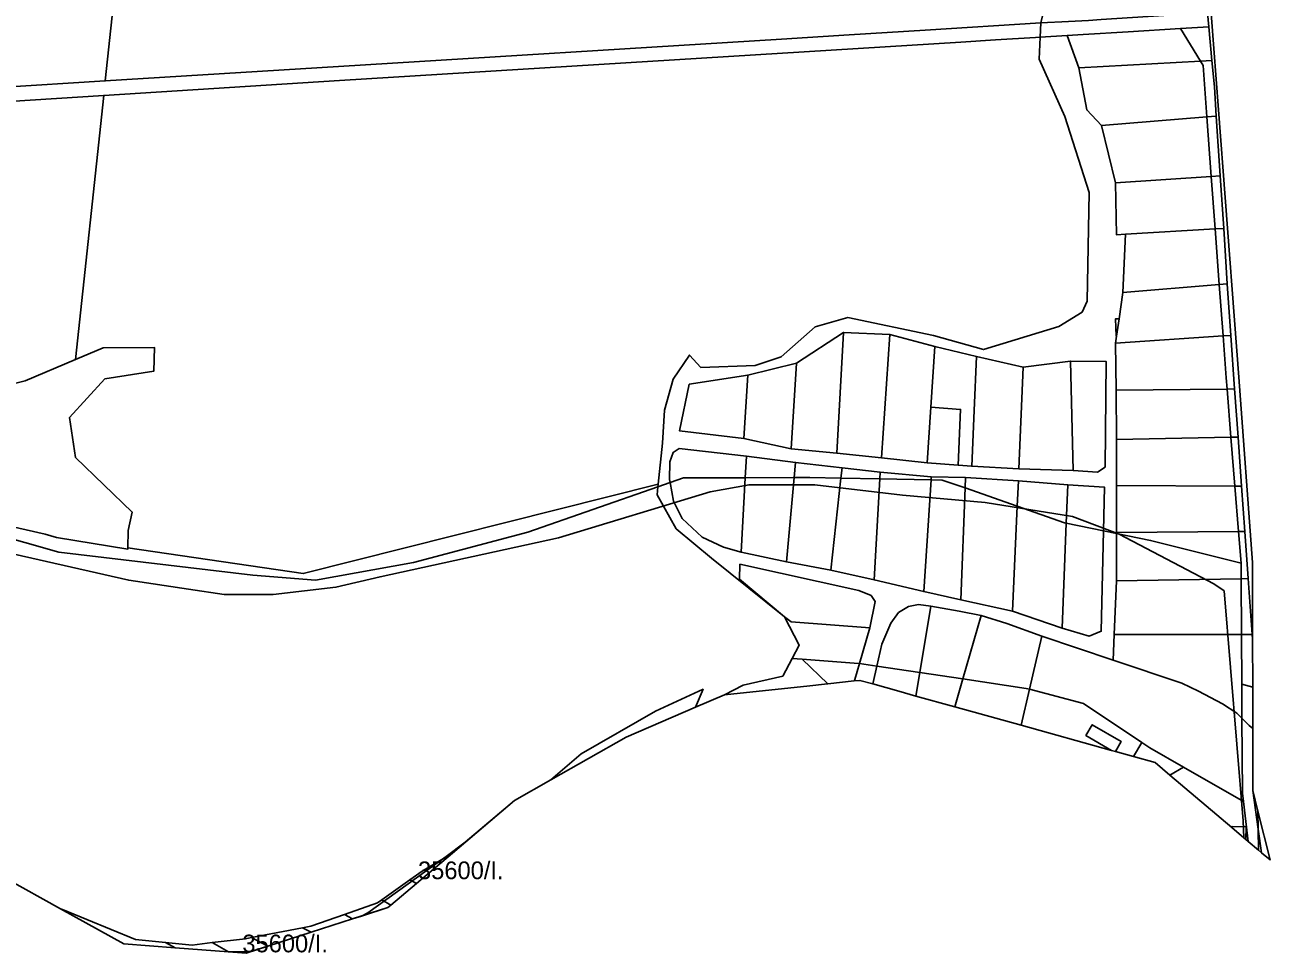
# Model space of a CAD drawing. Extents: x -537068 to -534056, y -1176840 to -1172401.
# Drawn here: x -535510.5 to -535158.7, y -1176840.3 to -1176578.1 of the extents above; entities that cross this region are included whole.
import ezdxf

# ---------------------------------------------------------------- set-up
doc = ezdxf.new("R2010")
doc.units = 0
for name, color, linetype in [('95630013', 7, 'Continuous'), ('95640013', 7, 'Continuous'), ('95660013', 7, 'Continuous')]:
    doc.layers.add(name, color=color, linetype=linetype)

msp = doc.modelspace()

# ---------------------------------------------------------------- linework, layer by layer
at = {"layer": '95630013'}
for points in [[(-535481.66, -1176536.93), (-535472.29, -1176540.41), (-535438.98, -1176545.89), (-535409.88, -1176540.34), (-535372.98, -1176516.36), (-535347.18, -1176505.79), (-535302.92, -1176487.67), (-535283.68, -1176476.52), (-535275.78, -1176469.69), (-535274.71, -1176470.43), (-535254.68, -1176465.39), (-535243.6, -1176462.73), (-535231.98, -1176465.74), (-535216.08, -1176481.68), (-535214.91, -1176500.06), (-535213.95, -1176515.16), (-535217.22, -1176552.4), (-535223.43, -1176577.55), (-535256.14, -1176579.59), (-535277.65, -1176580.92), (-535296.77, -1176582.11), (-535421.85, -1176589.87), (-535487.75, -1176593.96)], [(-535611.19, -1176513.92), (-535537.73, -1176516.12), (-535481.66, -1176536.93), (-535487.75, -1176593.96), (-535547.63, -1176597.67), (-535617.46, -1176602.04), (-535616.99, -1176606.16), (-535547.67, -1176601.79), (-535488.18, -1176598.05), (-535496.14, -1176672.63), (-535510.43, -1176678.69), (-535538.74, -1176685.61), (-535560.3, -1176696.02), (-535567.5, -1176700.1), (-535587.32, -1176690.88), (-535593.03, -1176689.8), (-535608.35, -1176682.47), (-535631.81, -1176671.18), (-535642.41, -1176641.9), (-535625.41, -1176591.75), (-535625.2, -1176543.89)], [(-535616.99, -1176606.16), (-535617.46, -1176602.04), (-535547.63, -1176597.67), (-535487.75, -1176593.96), (-535421.85, -1176589.87), (-535296.77, -1176582.11), (-535277.65, -1176580.92), (-535256.14, -1176579.59), (-535223.43, -1176577.55), (-535223.63, -1176581.58), (-535224.99, -1176581.66), (-535236.23, -1176582.36), (-535246.06, -1176582.97), (-535421.6, -1176593.86), (-535488.18, -1176598.05), (-535547.67, -1176601.79)], [(-535296.79, -1176671.9), (-535304.16, -1176674.29), (-535319.53, -1176674.86), (-535322.75, -1176671.4), (-535327.36, -1176678.19), (-535329.8, -1176686.93), (-535330.38, -1176696.29), (-535331.55, -1176707.87), (-535431.83, -1176733.13), (-535481.42, -1176725.84), (-535481.31, -1176720.98), (-535480.13, -1176715.73), (-535496.15, -1176700.28), (-535497.89, -1176689.03), (-535487.93, -1176678.11), (-535474.03, -1176675.92), (-535473.85, -1176669.28), (-535488.35, -1176669.33), (-535496.14, -1176672.63), (-535488.18, -1176598.05), (-535421.6, -1176593.86), (-535246.06, -1176582.97), (-535236.23, -1176582.36), (-535224.99, -1176581.66), (-535223.63, -1176581.58), (-535223.93, -1176587.8), (-535216.72, -1176603.99), (-535209.82, -1176625.43), (-535210.4, -1176656.13), (-535211.81, -1176659.3), (-535218.36, -1176663.32), (-535239.7, -1176669.83), (-535253.79, -1176665.86), (-535277.94, -1176660.78), (-535287.21, -1176663.4)], [(-535529.02, -1176718.5), (-535520.93, -1176718.34), (-535504.72, -1176722), (-535501.5, -1176722.89), (-535481.43, -1176726.23), (-535481.42, -1176725.84), (-535431.83, -1176733.13), (-535331.55, -1176707.87), (-535331.62, -1176708.58), (-535368.4, -1176721.4), (-535400.69, -1176729.98), (-535428.42, -1176735.02), (-535446.08, -1176733.53), (-535500.92, -1176727.08), (-535529.17, -1176719.06)], [(-535276.15, -1176763.46), (-535283.64, -1176764.25), (-535290.93, -1176757.29), (-535274.93, -1176758.51), (-535274.72, -1176758.54), (-535276.02, -1176763.01)], [(-535274.59, -1176763.29), (-535276.15, -1176763.46), (-535276.02, -1176763.01), (-535274.72, -1176758.54), (-535269.79, -1176759.27), (-535270.82, -1176763.9), (-535270.92, -1176764.31)], [(-535258.73, -1176767.71), (-535263.56, -1176766.36), (-535270.92, -1176764.31), (-535270.82, -1176763.9), (-535269.79, -1176759.27), (-535257.64, -1176761.08)], [(-535247.75, -1176770.77), (-535258.73, -1176767.71), (-535257.64, -1176761.08), (-535245.48, -1176762.88)], [(-535247.75, -1176770.77), (-535245.48, -1176762.88), (-535227.62, -1176765.54), (-535226.65, -1176765.8), (-535229.02, -1176775.98)], [(-535318.86, -1176765.79), (-535321.04, -1176770.89), (-535340.64, -1176779.33), (-535361.87, -1176791.41), (-535353.32, -1176784.03), (-535332.36, -1176771.96)], [(-535191.16, -1176786.53), (-535197.27, -1176784.83), (-535194.93, -1176780.88), (-535192.67, -1176782.39), (-535183.12, -1176787.84), (-535186.99, -1176790.06)], [(-535165.43, -1176804.7), (-535169.44, -1176804.52), (-535169.48, -1176804.89), (-535186.99, -1176790.06), (-535183.12, -1176787.84), (-535166.22, -1176797.48), (-535164.86, -1176808.8), (-535165.57, -1176808.2)], [(-535399.88, -1176820.68), (-535401.69, -1176819.62), (-535398.2, -1176817.14), (-535389.7, -1176812.08)], [(-535407.1, -1176826.78), (-535409.67, -1176825.3), (-535401.69, -1176819.62), (-535399.88, -1176820.68)], [(-535409.67, -1176825.3), (-535407.1, -1176826.78), (-535407.91, -1176827.46), (-535417.88, -1176830.67), (-535420.15, -1176829.4), (-535410.86, -1176826.14)], [(-535470.78, -1176837.3), (-535468.04, -1176838.81), (-535482.5, -1176837.72), (-535500.42, -1176827.8), (-535499.86, -1176827.98), (-535479.2, -1176836.47)], [(-535432, -1176833.2), (-535429.7, -1176832.76), (-535420.15, -1176829.4), (-535417.88, -1176830.67), (-535429.63, -1176834.45)], [(-535446.45, -1176835.95), (-535432, -1176833.2), (-535429.63, -1176834.45), (-535441.88, -1176838.39)], [(-535468.04, -1176838.81), (-535470.78, -1176837.3), (-535463.2, -1176838.05), (-535457.54, -1176837.38), (-535452.94, -1176839.95)], [(-535447.92, -1176840.33), (-535452.94, -1176839.95), (-535457.54, -1176837.38), (-535448.11, -1176836.27), (-535446.45, -1176835.95), (-535441.88, -1176838.39)]]:
    msp.add_lwpolyline(points, close=True, dxfattribs=at)
msp.add_lwpolyline([(-535529.17, -1176719.06), (-535500.92, -1176727.08), (-535446.08, -1176733.53), (-535428.42, -1176735.02), (-535400.69, -1176729.98), (-535368.4, -1176721.4), (-535331.62, -1176708.58), (-535331.85, -1176710.83), (-535326.51, -1176720.46), (-535316.52, -1176728.73), (-535295.86, -1176745.33), (-535291.71, -1176753.33), (-535293.7, -1176757.08), (-535296.36, -1176762.09), (-535307.57, -1176764.65), (-535312.79, -1176767.34), (-535321.04, -1176770.89), (-535318.86, -1176765.79), (-535332.36, -1176771.96), (-535353.32, -1176784.03), (-535361.87, -1176791.41), (-535372.13, -1176797.24), (-535389.7, -1176812.08), (-535398.2, -1176817.14), (-535401.69, -1176819.62), (-535409.67, -1176825.3), (-535410.86, -1176826.14), (-535420.15, -1176829.4), (-535429.7, -1176832.76), (-535432, -1176833.2), (-535446.45, -1176835.95), (-535448.11, -1176836.27), (-535457.54, -1176837.38), (-535463.2, -1176838.05), (-535470.78, -1176837.3), (-535479.2, -1176836.47), (-535499.86, -1176827.98), (-535500.42, -1176827.8), (-535515.98, -1176819.18)], dxfattribs=at)
at = {"layer": '95640013'}
msp.add_lwpolyline([(-535176.57, -1176558.65), (-535171.92, -1176619.39), (-535167.49, -1176677.59), (-535163.64, -1176729.95), (-535163.62, -1176751.68), (-535163.72, -1176750.32), (-535164.86, -1176734.55), (-535165.82, -1176721.23), (-535166.75, -1176708.4), (-535167.75, -1176694.55), (-535168.73, -1176680.96), (-535169.82, -1176665.9), (-535170.78, -1176651.22), (-535171.8, -1176635.6), (-535172.78, -1176620.73), (-535173.88, -1176603.89), (-535174.42, -1176595.65), (-535175.11, -1176588.15), (-535175.97, -1176578.68), (-535176.34, -1176574.66)], dxfattribs=at)
for points in [[(-535223.63, -1176581.58), (-535223.43, -1176577.55), (-535221.6, -1176577.44), (-535217.53, -1176577.23), (-535210.02, -1176576.83), (-535206.44, -1176576.6), (-535184.3, -1176575.17), (-535176.34, -1176574.66), (-535175.97, -1176578.68), (-535184.02, -1176579.16), (-535198.74, -1176580.03), (-535211.52, -1176580.83), (-535215.99, -1176581.11)], [(-535211.52, -1176580.83), (-535198.74, -1176580.03), (-535184.02, -1176579.16), (-535178.39, -1176588.33), (-535212.71, -1176590.22), (-535215.99, -1176581.11)], [(-535175.97, -1176578.68), (-535175.11, -1176588.15), (-535178.39, -1176588.33), (-535184.02, -1176579.16)], [(-535223.93, -1176587.8), (-535223.63, -1176581.58), (-535215.99, -1176581.11), (-535212.71, -1176590.22), (-535210.48, -1176602.15), (-535206.33, -1176606.49), (-535202.37, -1176622.77), (-535202.05, -1176637.45), (-535199.51, -1176637.24), (-535200.27, -1176653.74), (-535201.35, -1176661.12), (-535202.33, -1176661.13), (-535202.16, -1176666.09), (-535202.08, -1176666.09), (-535202.36, -1176667.98), (-535202.17, -1176681.29), (-535202.09, -1176695.22), (-535202.12, -1176708.23), (-535202.1, -1176721.52), (-535202.1, -1176721.79), (-535205.75, -1176721.04), (-535205.47, -1176708.74), (-535215.87, -1176708), (-535229.78, -1176706.91), (-535244.77, -1176705.96), (-535254.42, -1176705.75), (-535268.84, -1176704.5), (-535279.63, -1176703.27), (-535292.74, -1176701.71), (-535306.64, -1176699.94), (-535325.64, -1176697.75), (-535327.37, -1176698.9), (-535328.26, -1176701.54), (-535328.38, -1176706.51), (-535328.21, -1176707.39), (-535331.62, -1176708.58), (-535331.55, -1176707.87), (-535330.38, -1176696.29), (-535329.8, -1176686.93), (-535327.36, -1176678.19), (-535322.75, -1176671.4), (-535319.53, -1176674.86), (-535304.16, -1176674.29), (-535296.79, -1176671.9), (-535287.21, -1176663.4), (-535277.94, -1176660.78), (-535253.79, -1176665.86), (-535239.7, -1176669.83), (-535218.36, -1176663.32), (-535211.81, -1176659.3), (-535210.4, -1176656.13), (-535209.82, -1176625.43), (-535216.72, -1176603.99)], [(-535177.63, -1176589.57), (-535176.55, -1176604.11), (-535206.33, -1176606.49), (-535210.48, -1176602.15), (-535212.71, -1176590.22), (-535178.39, -1176588.33)], [(-535177.63, -1176589.57), (-535178.39, -1176588.33), (-535175.11, -1176588.15), (-535174.42, -1176595.65), (-535173.88, -1176603.89), (-535176.55, -1176604.11)], [(-535206.33, -1176606.49), (-535176.55, -1176604.11), (-535175.31, -1176620.91), (-535202.37, -1176622.77)], [(-535173.88, -1176603.89), (-535172.78, -1176620.73), (-535175.31, -1176620.91), (-535176.55, -1176604.11)], [(-535174.21, -1176635.74), (-535199.51, -1176637.24), (-535202.05, -1176637.45), (-535202.37, -1176622.77), (-535175.31, -1176620.91)], [(-535171.8, -1176635.6), (-535174.21, -1176635.74), (-535175.31, -1176620.91), (-535172.78, -1176620.73)], [(-535174.21, -1176635.74), (-535173.05, -1176651.42), (-535200.27, -1176653.74), (-535199.51, -1176637.24)], [(-535170.78, -1176651.22), (-535173.05, -1176651.42), (-535174.21, -1176635.74), (-535171.8, -1176635.6)], [(-535169.82, -1176665.9), (-535171.97, -1176665.93), (-535173.05, -1176651.42), (-535170.78, -1176651.22)], [(-535173.05, -1176651.42), (-535171.97, -1176665.93), (-535202.36, -1176667.98), (-535202.08, -1176666.09), (-535201.35, -1176661.12), (-535200.27, -1176653.74)], [(-535202.16, -1176666.09), (-535202.33, -1176661.13), (-535201.35, -1176661.12), (-535202.08, -1176666.09)], [(-535205.03, -1176673.17), (-535215.06, -1176673.08), (-535228.44, -1176674.8), (-535241.6, -1176671.83), (-535253.39, -1176668.93), (-535266.16, -1176665.62), (-535279.19, -1176665.01), (-535292.49, -1176673.65), (-535306.26, -1176677.05), (-535322.8, -1176679.63), (-535325.56, -1176692.78), (-535307.4, -1176694.94), (-535293.95, -1176697.87), (-535281.07, -1176699.1), (-535268.44, -1176700.42), (-535255.54, -1176701.84), (-535246.78, -1176702.5), (-535242.99, -1176702.78), (-535229.65, -1176703.56), (-535214.33, -1176704), (-535207.46, -1176704.48), (-535205.27, -1176703.05)], [(-535281.07, -1176699.1), (-535293.95, -1176697.87), (-535292.49, -1176673.65), (-535279.19, -1176665.01)], [(-535279.19, -1176665.01), (-535266.16, -1176665.62), (-535268.44, -1176700.42), (-535281.07, -1176699.1)], [(-535254.51, -1176686.1), (-535255.54, -1176701.84), (-535268.44, -1176700.42), (-535266.16, -1176665.62), (-535253.39, -1176668.93)], [(-535171.09, -1176677.82), (-535170.84, -1176680.99), (-535202.17, -1176681.29), (-535202.36, -1176667.98), (-535171.97, -1176665.93)], [(-535171.09, -1176677.82), (-535171.97, -1176665.93), (-535169.82, -1176665.9), (-535168.73, -1176680.96), (-535170.84, -1176680.99)], [(-535496.15, -1176700.28), (-535480.13, -1176715.73), (-535481.31, -1176720.98), (-535481.42, -1176725.84), (-535481.43, -1176726.23), (-535501.5, -1176722.89), (-535504.72, -1176722), (-535520.93, -1176718.34), (-535529.02, -1176718.5), (-535529.17, -1176719.06), (-535536.34, -1176717.02), (-535564.15, -1176706.5), (-535571.31, -1176702.26), (-535567.5, -1176700.1), (-535560.3, -1176696.02), (-535538.74, -1176685.61), (-535510.43, -1176678.69), (-535496.14, -1176672.63), (-535488.35, -1176669.33), (-535473.85, -1176669.28), (-535474.03, -1176675.92), (-535487.93, -1176678.11), (-535497.89, -1176689.03)], [(-535254.51, -1176686.1), (-535253.39, -1176668.93), (-535241.6, -1176671.83), (-535242.28, -1176687), (-535242.99, -1176702.78), (-535246.78, -1176702.5), (-535246.13, -1176686.72)], [(-535241.6, -1176671.83), (-535228.44, -1176674.8), (-535229.65, -1176703.56), (-535242.99, -1176702.78), (-535242.28, -1176687)], [(-535293.95, -1176697.87), (-535307.4, -1176694.94), (-535306.26, -1176677.05), (-535292.49, -1176673.65)], [(-535229.65, -1176703.56), (-535228.44, -1176674.8), (-535215.06, -1176673.08), (-535214.33, -1176704)], [(-535214.33, -1176704), (-535215.06, -1176673.08), (-535205.03, -1176673.17), (-535205.27, -1176703.05), (-535207.46, -1176704.48)], [(-535306.26, -1176677.05), (-535307.4, -1176694.94), (-535325.56, -1176692.78), (-535322.8, -1176679.63)], [(-535202.09, -1176695.22), (-535202.17, -1176681.29), (-535170.84, -1176680.99), (-535169.75, -1176694.58)], [(-535167.75, -1176694.55), (-535169.75, -1176694.58), (-535170.84, -1176680.99), (-535168.73, -1176680.96)], [(-535246.13, -1176686.72), (-535246.78, -1176702.5), (-535255.54, -1176701.84), (-535254.51, -1176686.1)], [(-535202.12, -1176708.23), (-535202.09, -1176695.22), (-535169.75, -1176694.58), (-535168.64, -1176708.39)], [(-535167.75, -1176694.55), (-535166.75, -1176708.4), (-535168.64, -1176708.39), (-535169.75, -1176694.58)], [(-535306.64, -1176699.94), (-535306.98, -1176706.04), (-535324.38, -1176706.06), (-535328.21, -1176707.39), (-535328.38, -1176706.51), (-535328.26, -1176701.54), (-535327.37, -1176698.9), (-535325.64, -1176697.75)], [(-535293.14, -1176706.02), (-535306.98, -1176706.04), (-535306.64, -1176699.94), (-535292.74, -1176701.71)], [(-535279.95, -1176706.17), (-535288.68, -1176706.02), (-535293.14, -1176706.02), (-535292.74, -1176701.71), (-535279.63, -1176703.27)], [(-535268.94, -1176706.37), (-535279.95, -1176706.17), (-535279.63, -1176703.27), (-535268.84, -1176704.5)], [(-535202.7, -1176750.35), (-535202.98, -1176757.61), (-535223.17, -1176750.83), (-535233.07, -1176747.2), (-535240.33, -1176744.93), (-535246.56, -1176743.69), (-535254.55, -1176742.29), (-535258.05, -1176741.88), (-535260.85, -1176742.4), (-535263.65, -1176744.08), (-535265.87, -1176747.08), (-535268.41, -1176753.09), (-535269.79, -1176759.27), (-535274.72, -1176758.54), (-535271.79, -1176748.42), (-535270.25, -1176741), (-535271.42, -1176739.32), (-535274.83, -1176737.85), (-535308.45, -1176730.5), (-535308.59, -1176734.68), (-535295.86, -1176745.33), (-535316.52, -1176728.73), (-535326.51, -1176720.46), (-535331.85, -1176710.83), (-535331.62, -1176708.58), (-535328.21, -1176707.39), (-535327.2, -1176712.65), (-535324.79, -1176717.58), (-535319.1, -1176722.79), (-535313.08, -1176725.67), (-535308.15, -1176727.06), (-535295.31, -1176729.82), (-535282.76, -1176732.18), (-535270.5, -1176734.84), (-535256.55, -1176738.19), (-535246.06, -1176740.51), (-535231.42, -1176743.69), (-535217.4, -1176748.57), (-535209.79, -1176750.8), (-535206.41, -1176749.42), (-535205.75, -1176721.04), (-535202.1, -1176721.79), (-535202.1, -1176735.17)], [(-535328.21, -1176707.39), (-535324.38, -1176706.06), (-535306.98, -1176706.04), (-535308.15, -1176727.06), (-535313.08, -1176725.67), (-535319.1, -1176722.79), (-535324.79, -1176717.58), (-535327.2, -1176712.65)], [(-535293.14, -1176706.02), (-535295.31, -1176729.82), (-535308.15, -1176727.06), (-535306.98, -1176706.04)], [(-535295.31, -1176729.82), (-535293.14, -1176706.02), (-535288.68, -1176706.02), (-535279.95, -1176706.17), (-535282.76, -1176732.18)], [(-535282.76, -1176732.18), (-535279.95, -1176706.17), (-535268.94, -1176706.37), (-535270.5, -1176734.84)], [(-535270.5, -1176734.84), (-535268.94, -1176706.37), (-535254.48, -1176706.62), (-535256.55, -1176738.19)], [(-535254.42, -1176705.75), (-535254.48, -1176706.62), (-535268.94, -1176706.37), (-535268.84, -1176704.5)], [(-535246.06, -1176740.51), (-535256.55, -1176738.19), (-535254.48, -1176706.62), (-535251.31, -1176706.68), (-535244.88, -1176708.93)], [(-535251.31, -1176706.68), (-535254.48, -1176706.62), (-535254.42, -1176705.75), (-535244.77, -1176705.96), (-535244.88, -1176708.93)], [(-535229.78, -1176706.91), (-535230.1, -1176714.11), (-535244.88, -1176708.93), (-535244.77, -1176705.96)], [(-535215.87, -1176708), (-535216.28, -1176718.88), (-535216.76, -1176718.78), (-535230.1, -1176714.11), (-535229.78, -1176706.91)], [(-535231.42, -1176743.69), (-535246.06, -1176740.51), (-535244.88, -1176708.93), (-535230.1, -1176714.11)], [(-535205.75, -1176721.04), (-535216.28, -1176718.88), (-535215.87, -1176708), (-535205.47, -1176708.74)], [(-535202.12, -1176708.23), (-535168.64, -1176708.39), (-535167.62, -1176721.25), (-535202.1, -1176721.52)], [(-535166.75, -1176708.4), (-535165.82, -1176721.23), (-535167.62, -1176721.25), (-535168.64, -1176708.39)], [(-535216.76, -1176718.78), (-535216.28, -1176718.88), (-535217.4, -1176748.57), (-535231.42, -1176743.69), (-535230.1, -1176714.11)], [(-535206.41, -1176749.42), (-535209.79, -1176750.8), (-535217.4, -1176748.57), (-535216.28, -1176718.88), (-535205.75, -1176721.04)], [(-535166.9, -1176730.2), (-535192.47, -1176723.76), (-535202.1, -1176721.79), (-535202.1, -1176721.52), (-535167.62, -1176721.25)], [(-535166.87, -1176734.58), (-535166.9, -1176730.2), (-535167.62, -1176721.25), (-535165.82, -1176721.23), (-535164.86, -1176734.55)], [(-535202.1, -1176735.17), (-535202.1, -1176721.79), (-535192.47, -1176723.76), (-535166.9, -1176730.2), (-535166.87, -1176734.58)], [(-535294.03, -1176746.78), (-535295.86, -1176745.33), (-535308.59, -1176734.68), (-535308.45, -1176730.5), (-535274.83, -1176737.85), (-535271.42, -1176739.32), (-535270.25, -1176741), (-535271.79, -1176748.42)], [(-535166.78, -1176750.32), (-535202.7, -1176750.35), (-535202.1, -1176735.17), (-535166.87, -1176734.58)], [(-535166.87, -1176734.58), (-535164.86, -1176734.55), (-535163.72, -1176750.32), (-535166.78, -1176750.32)], [(-535260.85, -1176742.4), (-535258.05, -1176741.88), (-535254.55, -1176742.29), (-535257.64, -1176761.08), (-535269.79, -1176759.27), (-535268.41, -1176753.09), (-535265.87, -1176747.08), (-535263.65, -1176744.08)], [(-535246.56, -1176743.69), (-535240.33, -1176744.93), (-535245.48, -1176762.88), (-535257.64, -1176761.08), (-535254.55, -1176742.29)], [(-535291.71, -1176753.33), (-535295.86, -1176745.33), (-535294.03, -1176746.78), (-535271.79, -1176748.42), (-535274.72, -1176758.54), (-535274.93, -1176758.51), (-535290.93, -1176757.29), (-535293.7, -1176757.08)], [(-535245.48, -1176762.88), (-535240.33, -1176744.93), (-535233.07, -1176747.2), (-535223.17, -1176750.83), (-535226.65, -1176765.8), (-535227.62, -1176765.54)], [(-535183.67, -1176764.09), (-535178.89, -1176766.33), (-535172.17, -1176769.88), (-535168.13, -1176772.55), (-535166.63, -1176774), (-535166.5, -1176795.11), (-535166.22, -1176797.48), (-535183.12, -1176787.84), (-535192.67, -1176782.39), (-535194.93, -1176780.88), (-535211.39, -1176769.83), (-535226.65, -1176765.8), (-535223.17, -1176750.83), (-535202.98, -1176757.61)], [(-535172.17, -1176769.88), (-535178.89, -1176766.33), (-535183.67, -1176764.09), (-535202.98, -1176757.61), (-535202.7, -1176750.35), (-535166.78, -1176750.32), (-535166.69, -1176764.4), (-535166.63, -1176774), (-535168.13, -1176772.55)], [(-535166.69, -1176764.4), (-535166.78, -1176750.32), (-535163.72, -1176750.32), (-535163.62, -1176751.68), (-535163.61, -1176765.23)], [(-535283.64, -1176764.25), (-535284.58, -1176764.35), (-535288.69, -1176764.79), (-535312.79, -1176767.34), (-535307.57, -1176764.65), (-535296.36, -1176762.09), (-535293.7, -1176757.08), (-535290.93, -1176757.29)], [(-535200.73, -1176780.59), (-535208.91, -1176775.84), (-535210.74, -1176778.85), (-535203.48, -1176783.1), (-535229.02, -1176775.98), (-535226.65, -1176765.8), (-535211.39, -1176769.83), (-535194.93, -1176780.88), (-535197.27, -1176784.83), (-535202.4, -1176783.4)], [(-535163.6, -1176776.92), (-535164.56, -1176776), (-535166.63, -1176774), (-535166.69, -1176764.4), (-535163.61, -1176765.23)], [(-535163.59, -1176794.38), (-535162.06, -1176805.28), (-535161.98, -1176811.24), (-535164.86, -1176808.8), (-535166.22, -1176797.48), (-535166.5, -1176795.11), (-535166.63, -1176774), (-535164.56, -1176776), (-535163.6, -1176776.92)], [(-535208.91, -1176775.84), (-535200.73, -1176780.59), (-535202.4, -1176783.4), (-535203.48, -1176783.1), (-535210.74, -1176778.85)], [(-535163.59, -1176794.38), (-535162.13, -1176800.24), (-535162.06, -1176805.28)], [(-535158.69, -1176814.03), (-535161.12, -1176811.97), (-535162.06, -1176805.28), (-535162.13, -1176800.24)], [(-535169.44, -1176804.52), (-535165.43, -1176804.7), (-535165.57, -1176808.2), (-535169.48, -1176804.89)], [(-535161.98, -1176811.24), (-535162.06, -1176805.28), (-535161.12, -1176811.97)]]:
    msp.add_lwpolyline(points, close=True, dxfattribs=at)
at = {"layer": '95660013'}
for points in [[(-535176.57, -1176558.65), (-535171.92, -1176619.39), (-535167.49, -1176677.59), (-535163.64, -1176729.95), (-535163.62, -1176751.68), (-535163.61, -1176765.23), (-535163.6, -1176776.92), (-535163.59, -1176794.38), (-535162.13, -1176800.24), (-535158.69, -1176814.03), (-535161.12, -1176811.97), (-535161.98, -1176811.24), (-535164.86, -1176808.8), (-535165.57, -1176808.2), (-535166.12, -1176807.73), (-535166.31, -1176803), (-535171.62, -1176738), (-535174.62, -1176736), (-535201.37, -1176722), (-535214.5, -1176717), (-535239.19, -1176713), (-535262.5, -1176711), (-535287.31, -1176708), (-535305.87, -1176708), (-535316.87, -1176710), (-535359.69, -1176723), (-535410.12, -1176734), (-535422.62, -1176737), (-535440.31, -1176739), (-535454.19, -1176739), (-535464.29, -1176737.5), (-535481.12, -1176735), (-535529.81, -1176724)], [(-535529.81, -1176724), (-535481.12, -1176735), (-535464.29, -1176737.5), (-535454.19, -1176739), (-535440.31, -1176739), (-535422.62, -1176737), (-535410.12, -1176734), (-535359.69, -1176723), (-535316.87, -1176710), (-535305.87, -1176708), (-535287.31, -1176708), (-535262.5, -1176711), (-535239.19, -1176713), (-535214.5, -1176717), (-535201.37, -1176722), (-535174.62, -1176736), (-535171.62, -1176738), (-535166.31, -1176803), (-535166.12, -1176807.73), (-535169.48, -1176804.89), (-535186.99, -1176790.06), (-535191.16, -1176786.53), (-535197.27, -1176784.83), (-535202.4, -1176783.4), (-535203.48, -1176783.1), (-535229.02, -1176775.98), (-535247.75, -1176770.77), (-535258.73, -1176767.71), (-535263.56, -1176766.36), (-535270.92, -1176764.31), (-535274.59, -1176763.29), (-535276.15, -1176763.46), (-535283.64, -1176764.25), (-535284.58, -1176764.35), (-535288.69, -1176764.79), (-535312.79, -1176767.34), (-535321.04, -1176770.89), (-535340.64, -1176779.33), (-535361.87, -1176791.41), (-535372.13, -1176797.24), (-535386.08, -1176809.02), (-535391.5, -1176813), (-535413.62, -1176829), (-535415.4, -1176829.87), (-535417.88, -1176830.67), (-535429.63, -1176834.45), (-535441.88, -1176838.39), (-535446.89, -1176840), (-535452.28, -1176840), (-535452.94, -1176839.95), (-535468.04, -1176838.81), (-535482.5, -1176837.72), (-535500.42, -1176827.8), (-535515.98, -1176819.18)]]:
    msp.add_lwpolyline(points, dxfattribs=at)
for points in [[(-535407.91, -1176827.46), (-535415.4, -1176829.87), (-535413.62, -1176829), (-535391.5, -1176813), (-535386.08, -1176809.02), (-535389.7, -1176812.08), (-535399.88, -1176820.68), (-535407.1, -1176826.78)], [(-535446.89, -1176840), (-535447.92, -1176840.33), (-535452.28, -1176840)]]:
    msp.add_lwpolyline(points, close=True, dxfattribs=at)

# ---------------------------------------------------------------- texts
for p in [(-535399.41, -1176819.45), (-535449.03, -1176840.11)]:
    msp.add_text('35600/I.', height=5, rotation=0, dxfattribs=at).set_placement(p)

doc.saveas('drawing.dxf')
